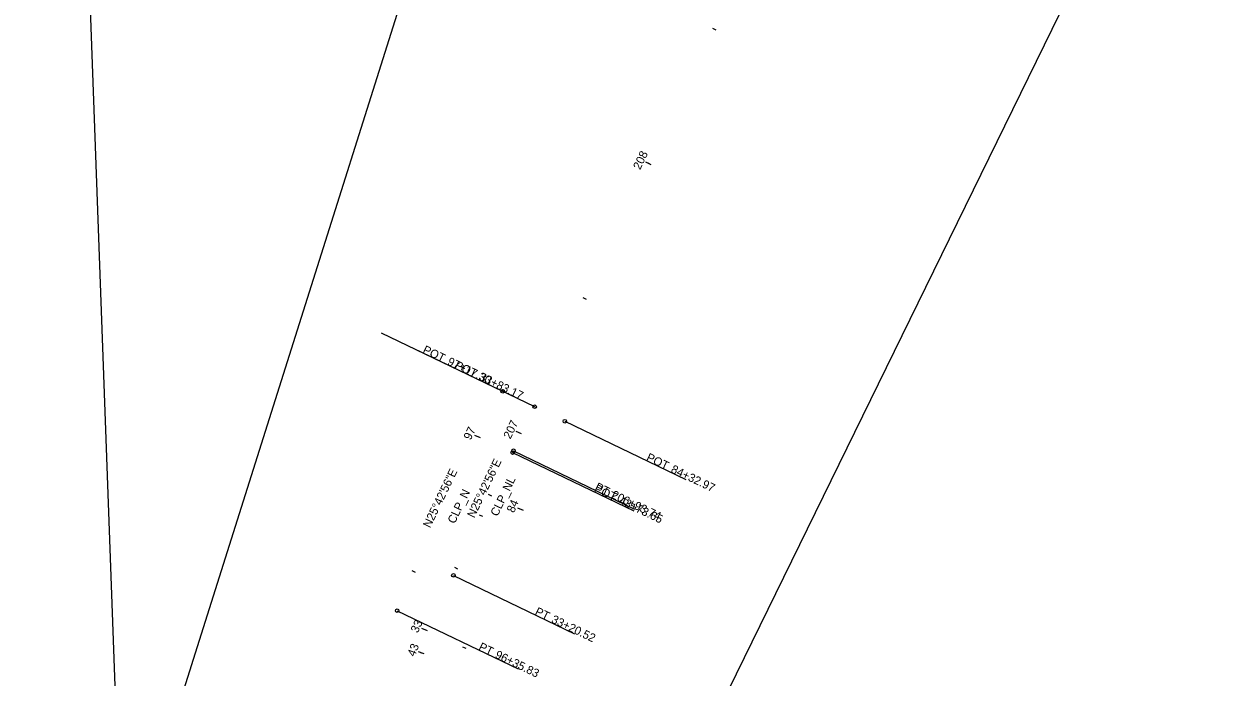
# Model space of a CAD drawing. Extents: x 1564517 to 1565226, y 635740 to 637455.
# Drawn here: x 1564828.9 to 1565225.9, y 636823.1 to 637041.9 of the extents above; entities that cross this region are included whole.
import ezdxf

# ---------------------------------------------------------------- set-up
doc = ezdxf.new("R2010")
doc.units = 0
for name, color, linetype in [('GE_P_Alignment_1000_Cardinal_Points', 7, 'Continuous'), ('GE_P_Alignment_500_Cardinal_Points', 7, 'Continuous'), ('GK_Drainage_Nodes', 7, 'Continuous'), ('SC_Scratch10', 7, 'Continuous'), ('TX_P_1000', 7, 'Continuous'), ('UT_P_Water', 7, 'Continuous'), ('UT_P_Water_Cells', 7, 'Continuous'), ('UT_X_Electric', 7, 'Continuous'), ('UT_X_Sanitary_Pressure_Line', 7, 'Continuous'), ('UT_X_Water_Cells', 7, 'Continuous')]:
    doc.layers.add(name, color=color, linetype=linetype)

msp = doc.modelspace()

# ---------------------------------------------------------------- linework, layer by layer
at = {"layer": 'GE_P_Alignment_1000_Cardinal_Points'}
msp.add_line((1564992.79, 636898.95), (1565033.33, 636879.42), dxfattribs=at)
msp.add_circle((1564992.79, 636898.95), 0.6, dxfattribs=at)
at = {"layer": 'GE_P_Alignment_500_Cardinal_Points'}
msp.add_line((1564992.79, 636898.95), (1565033.33, 636879.42), dxfattribs=at)
msp.add_circle((1564992.79, 636898.95), 0.6, dxfattribs=at)
at = {"layer": 'TX_P_1000'}
for p, q in [((1564999.88, 636913.69), (1564959.34, 636933.21)), ((1564992.5, 636898.35), (1565033.04, 636878.82)), ((1564992.79, 636898.95), (1565033.33, 636879.42)), ((1564972.7, 636857.24), (1565013.24, 636837.71))]:
    msp.add_line(p, q, dxfattribs=at)
at = {"layer": 'UT_P_Water_Cells'}
for p, q in [((1565038.89, 636994.68), (1565037.81, 636995.2)), ((1564989.21, 636918.83), (1564948.67, 636938.35)), ((1564999.88, 636913.69), (1564959.34, 636933.21)), ((1565009.97, 636908.83), (1565050.51, 636889.31)), ((1564981.71, 636903.24), (1564980.63, 636903.76)), ((1564995.5, 636904.58), (1564994.42, 636905.1)), ((1564992.5, 636898.35), (1565033.04, 636878.82)), ((1564996.13, 636878.9), (1564995.03, 636879.39)), ((1564972.7, 636857.24), (1565013.24, 636837.71)), ((1564953.86, 636845.42), (1564994.41, 636825.9)), ((1564963.98, 636838.67), (1564962.89, 636839.17)), ((1564962.91, 636830.92), (1564961.8, 636831.36))]:
    msp.add_line(p, q, dxfattribs=at)
for centre in [(1564989.21, 636918.83), (1564999.88, 636913.69), (1565009.97, 636908.83), (1564992.5, 636898.35), (1564972.7, 636857.24), (1564953.86, 636845.42)]:
    msp.add_circle(centre, 0.6, dxfattribs=at)
at = {"layer": 'UT_X_Electric'}
for points in [[(1564682.06, 636752.05), (1564842.01, 636748.56), (1564861.83, 636755.87), (1564842.73, 637279.63), (1564517.04, 637293.63), (1564662.12, 636876.82)], [(1564858.24, 636742.53), (1565001.39, 636689.39), (1565225.94, 637148.15), (1565017.94, 637248.32)]]:
    msp.add_lwpolyline(points, close=True, dxfattribs=at)
at = {"layer": 'UT_X_Sanitary_Pressure_Line'}
for p, q in [((1564989.21, 636918.83), (1564948.67, 636938.35)), ((1564999.88, 636913.69), (1564959.34, 636933.21)), ((1565009.97, 636908.83), (1565050.51, 636889.31)), ((1564992.5, 636898.35), (1565033.04, 636878.82)), ((1564972.7, 636857.24), (1565013.24, 636837.71)), ((1564953.86, 636845.42), (1564994.41, 636825.9))]:
    msp.add_line(p, q, dxfattribs=at)
for centre in [(1564989.21, 636918.83), (1564999.88, 636913.69), (1565009.97, 636908.83), (1564992.5, 636898.35), (1564972.7, 636857.24), (1564953.86, 636845.42)]:
    msp.add_circle(centre, 0.6, dxfattribs=at)
at = {"layer": 'UT_X_Water_Cells'}
for p, q in [((1565060.59, 637039.73), (1565059.51, 637040.25)), ((1565038.89, 636994.68), (1565037.09, 636995.55)), ((1565017.2, 636949.63), (1565016.12, 636950.15)), ((1564981.71, 636903.24), (1564979.91, 636904.11)), ((1564995.5, 636904.58), (1564993.7, 636905.45)), ((1564985.49, 636883.8), (1564984.41, 636884.32)), ((1564996.13, 636878.9), (1564994.3, 636879.71)), ((1564982.48, 636876.93), (1564981.39, 636877.42)), ((1564960.01, 636858.19), (1564958.93, 636858.71)), ((1564974.22, 636859.34), (1564973.13, 636859.84)), ((1564963.98, 636838.67), (1564962.16, 636839.5)), ((1564962.91, 636830.92), (1564961.05, 636831.66)), ((1564976.98, 636832.72), (1564975.86, 636833.15))]:
    msp.add_line(p, q, dxfattribs=at)
msp.add_circle((1564999.88, 636913.69), 0.6, dxfattribs=at)

# ---------------------------------------------------------------- texts
at = {"layer": 'GE_P_Alignment_1000_Cardinal_Points'}
for s, p in [('PT', (1565019.81, 636885.93)), ('206+93.74', (1565025.3, 636883.29))]:
    msp.add_text(s, height=2.8, rotation=334.2844, dxfattribs=at).set_placement(p)
at = {"layer": 'GE_P_Alignment_500_Cardinal_Points'}
for s, p in [('PT', (1565019.81, 636885.93)), ('206+93.74', (1565025.3, 636883.29))]:
    msp.add_text(s, height=2.8, rotation=334.2844, dxfattribs=at).set_placement(p)
at = {"layer": 'GK_Drainage_Nodes'}
for s, p in [('N25°42\'56"E', (1564979.64, 636876.26)), ('N25°42\'56"E', (1564964.88, 636872.92)), ('CLP_NL', (1564987.44, 636876.77)), ('CLP_N', (1564973.1, 636874.31))]:
    msp.add_text(s, height=2.8, rotation=64.2844, dxfattribs=at).set_placement(p)
at = {"layer": 'SC_Scratch10'}
for s, p in [('N25°42\'56"E', (1564979.64, 636876.26)), ('N25°42\'56"E', (1564964.88, 636872.92)), ('CLP_NL', (1564987.44, 636876.77)), ('CLP_N', (1564973.1, 636874.31))]:
    msp.add_text(s, height=2.8, rotation=64.2844, dxfattribs=at).set_placement(p)
at = {"layer": 'UT_P_Water'}
for s, p in [('N25°42\'56"E', (1564979.64, 636876.26)), ('N25°42\'56"E', (1564964.88, 636872.92)), ('CLP_NL', (1564987.44, 636876.77)), ('CLP_N', (1564973.1, 636874.31))]:
    msp.add_text(s, height=2.8, rotation=64.2844, dxfattribs=at).set_placement(p)
at = {"layer": 'UT_P_Water_Cells'}
for s, p in [('POT', (1564962.18, 636931.84)), ('97+17.30', (1564970.41, 636927.88)), ('POT', (1564972.86, 636926.7)), ('33+83.17', (1564981.08, 636922.74)), ('POT', (1565036.99, 636895.81)), ('84+32.97', (1565045.22, 636891.85)), ('POT', (1565019.53, 636885.33)), ('43+73.65', (1565027.75, 636881.37)), ('PT', (1564999.73, 636844.22)), ('33+20.52', (1565005.21, 636841.58)), ('PT', (1564980.89, 636832.4)), ('96+35.83', (1564986.37, 636829.76))]:
    msp.add_text(s, height=2.8, rotation=334.2844, dxfattribs=at).set_placement(p)
at = {"layer": 'UT_X_Sanitary_Pressure_Line'}
for s, p in [('POT', (1564962.18, 636931.84)), ('97+17.30', (1564970.41, 636927.88)), ('POT', (1564972.86, 636926.7)), ('33+83.17', (1564981.08, 636922.74)), ('POT', (1565036.99, 636895.81)), ('84+32.97', (1565045.22, 636891.85)), ('POT', (1565019.53, 636885.33)), ('43+73.65', (1565027.75, 636881.37)), ('PT', (1564999.73, 636844.22)), ('33+20.52', (1565005.21, 636841.58)), ('PT', (1564980.89, 636832.4)), ('96+35.83', (1564986.37, 636829.76))]:
    msp.add_text(s, height=2.8, rotation=334.2844, dxfattribs=at).set_placement(p)
at = {"layer": 'UT_X_Water_Cells'}
for s, rotation, p in [('208', 64.2844, (1565035.17, 636992.83)), ('97', 64.2844, (1564978.44, 636902.32)), ('207', 64.2844, (1564991.76, 636902.68)), ('84', 66.0976, (1564992.93, 636877.97)), ('33', 65.4126, (1564960.76, 636837.75)), ('43', 68.3342, (1564959.74, 636829.84))]:
    msp.add_text(s, height=2.8, rotation=rotation, dxfattribs=at).set_placement(p)

doc.saveas('drawing.dxf')
